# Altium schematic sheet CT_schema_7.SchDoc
size 388 x 301 mm
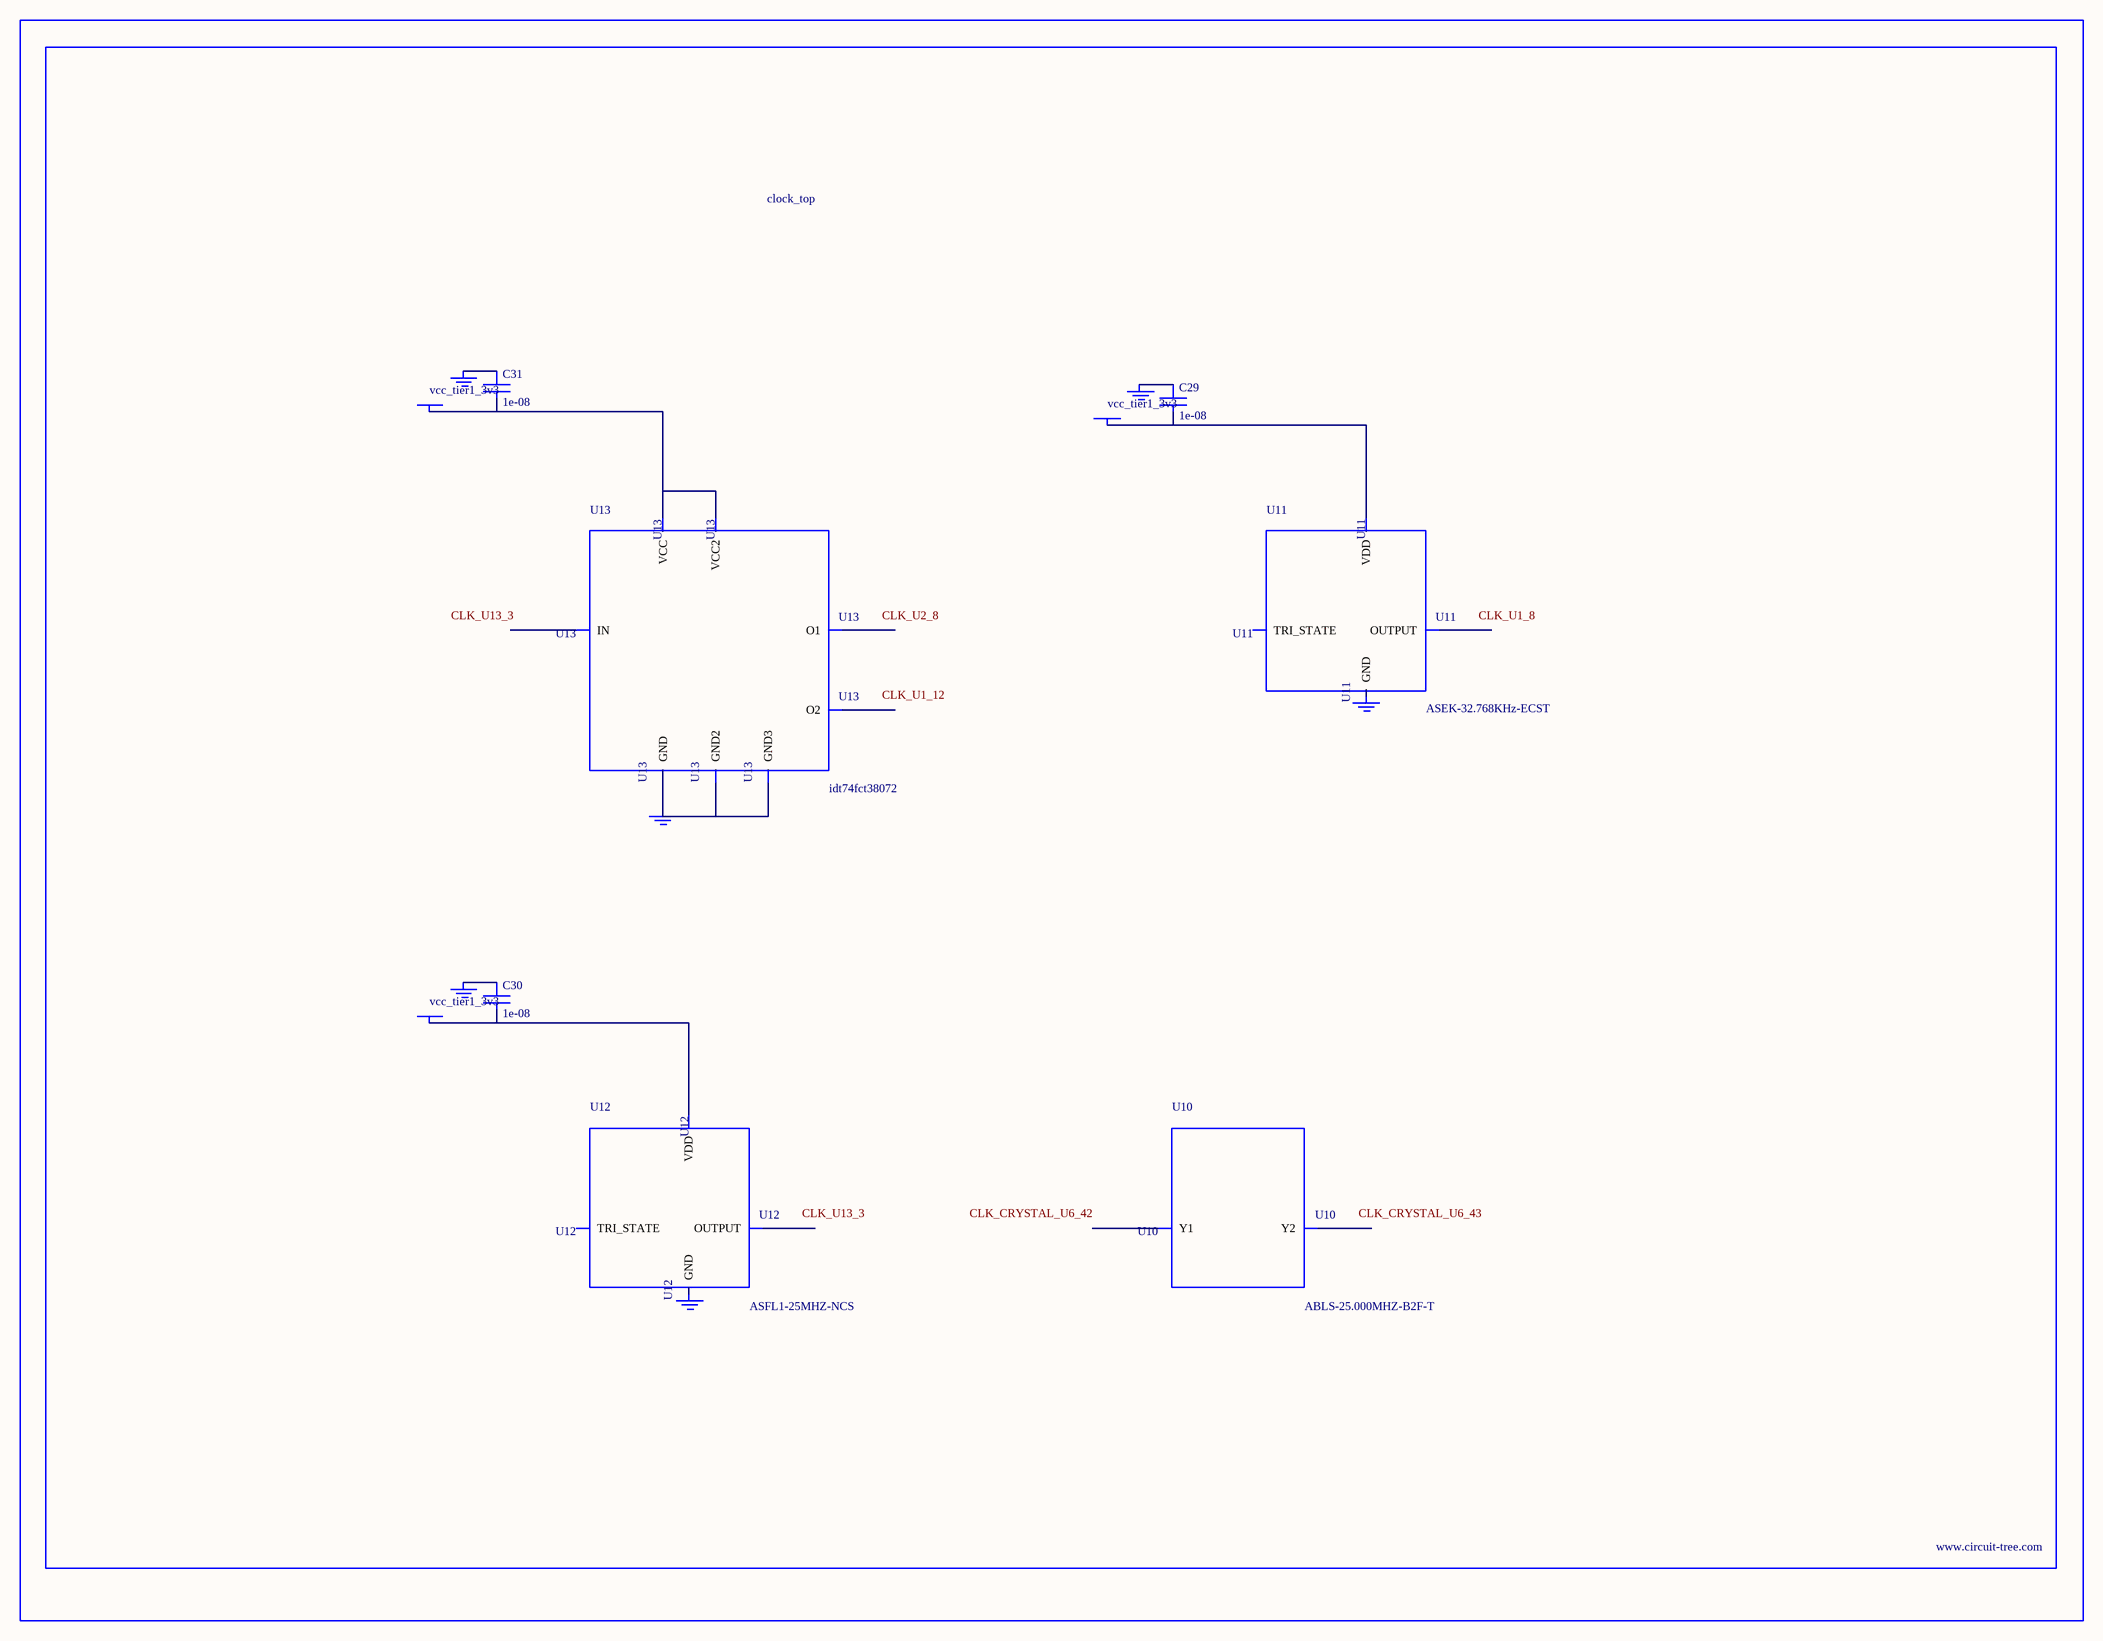
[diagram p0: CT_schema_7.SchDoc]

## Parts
BORDER6  (no value)
C29  1e-08  [C0402]
C30  1e-08  [C0402]
C31  1e-08  [C0402]
GND_INSTANCE_6_0  (no value)
GND_INSTANCE_6_1  (no value)
GND_INSTANCE_6_2  (no value)
GND_INSTANCE_6_3  (no value)
GND_INSTANCE_6_4  (no value)
GND_INSTANCE_6_5  (no value)
POWER_INSTANCE_6_0  vcc_tier1_3v3
POWER_INSTANCE_6_1  vcc_tier1_3v3
POWER_INSTANCE_6_2  vcc_tier1_3v3
U10  ABLS-25.000MHZ-B2F-T  [ABLS-25.000MHZ-B2F-T]
U11  ASEK-32.768KHz-ECST  [ASEK]
U12  ASFL1-25MHZ-NCS  [ASFL1]
U13  idt74fct38072  [IDT74FCT38072]

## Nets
NetC29_1: C29.1 GND_INSTANCE_6_0.0(GND)
NetC29_2: C29.2 POWER_INSTANCE_6_0.0(PWR) U11.4(VDD)
NetC30_1: C30.1 GND_INSTANCE_6_2.0(GND)
NetC30_2: C30.2 POWER_INSTANCE_6_1.0(PWR) U12.4(VDD)
NetC31_1: C31.1 GND_INSTANCE_6_4.0(GND)
NetC31_2: C31.2 POWER_INSTANCE_6_2.0(PWR) U13.1(VCC) U13.2(VCC2)
NetGND_INSTANCE_6_5_0: GND_INSTANCE_6_5.0(GND) U13.4(GND) U13.5(GND2) U13.8(GND3)

Not connected (* = marked no-connect by the designer): GND_INSTANCE_6_1 0(GND); GND_INSTANCE_6_3 0(GND); U10 1(Y1) 2(Y2); U11 1(TRI_STATE) 2(GND) 3(OUTPUT); U12 1(TRI_STATE) 2(GND) 3(OUTPUT); U13 3(IN) 6(O2) 7(O1)

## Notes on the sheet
- Labels drawn without touching a wire or pin: CLK_CRYSTAL_U6_42, CLK_CRYSTAL_U6_43, CLK_U1_8, CLK_U1_12, CLK_U2_8, CLK_U13_3

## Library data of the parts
BORDER6 = BORDER_PAGE6
C29-C31 = C0402C103K3RAC
GND_INSTANCE_6_0-GND_INSTANCE_6_5 = GND
POWER_INSTANCE_6_0-POWER_INSTANCE_6_2 = PWR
